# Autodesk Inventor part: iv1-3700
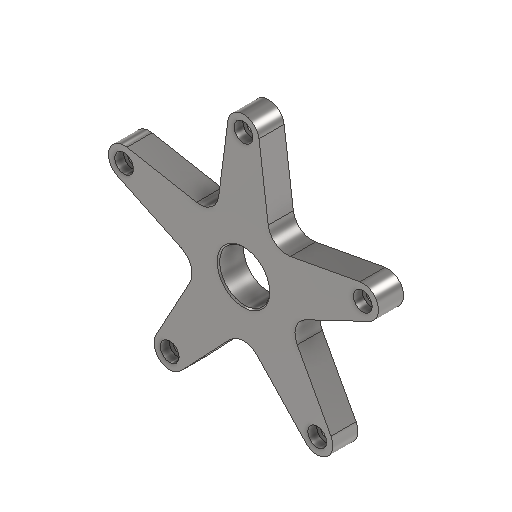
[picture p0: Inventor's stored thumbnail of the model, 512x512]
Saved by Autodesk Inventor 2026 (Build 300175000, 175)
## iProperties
Created: 2022-01
Part Number: iv1-3700
Material: Steel, Mild
Document SubType Name: Modeling
Designer: Lars Bertram Pedersen
Density: 7.85 g/cm^3
Appearance: Semi-Polished
Mass: 2365.55 g
Surface Area: 537.033 cm^2
Volume: 301.343 cm^3
Author: Lars Bertram Pedersen
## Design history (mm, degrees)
sketch "Sketch1"
  geometry: L1 (-12.393, 101.632)-(-25.773, 0); L2 (12.393, 101.632)-(25.773, 0); L3 (-25.773, 0)-(25.773, 0); C1 r 20 at (0, 0); A1 r 12.5 centre (0, 100) between (12.476, 99.219) and (-12.476, 99.219); A2 r 100 centre (0, 0) between (0, 100) and (-12.476, 99.219); 1 further point
  constraints: 7 point on circle, 6 end point, 3 centre point, 3 horizontal alignment, 2 coincident, 2 tangent, 1 horizontal, 1 vertical alignment
  dimensions: "d0" = 200 diameter of A2; "d1" = 40 diameter of C1; "d2" = 12.5 radius of A1; "d3" = 15 deg angle of L2 L1
extrude "Extrusion1" new body sketch "Sketch1" distance "d4" = 20; taper "d5" = 0 deg
pattern_circular "Circular Pattern1" dims angle "d7" = 360 deg
fillet "Fillet1" dims "d9" = 15
sketch "Sketch3"
  geometry: C1 r 20 at (0, 0); 1 further point
  constraints: 1 centre point, 1 coincident
  dimensions: "d17" = 40 diameter of C1
extrude "Extrusion2" cut sketch "Sketch3" extent not by distance; stored distance "d18" = 0; taper "d19" = 0 deg
sketch "Sketch2"
  geometry: L1 (-37.361, 32.912)-(-92.828, 43.192) reference; L2 (-100.487, 19.619)-(-49.571, -4.666) reference; L3 (-42.847, -25.362)-(-69.764, -74.937) reference; L4 (-49.711, -89.506)-(-10.881, -48.587) reference; L5 (10.881, -48.587)-(49.711, -89.506) reference; L6 (69.764, -74.937)-(42.847, -25.362) reference; L7 (49.571, -4.666)-(100.487, 19.619) reference; L8 (92.828, 43.192)-(37.361, 32.912) reference; L9 (19.756, 45.703)-(12.393, 101.632) reference; L10 (-12.393, 101.632)-(-19.756, 45.703) reference; A1 r 12.5 centre (-95.106, 30.902) between (-92.828, 43.192) and (-100.487, 19.619) reference; A2 r 15 centre (-56.029, -18.205) between (-42.847, -25.362) and (-49.571, -4.666) reference; A3 r 12.5 centre (-58.779, -80.902) between (-69.764, -74.937) and (-49.711, -89.506) reference; A4 r 15 centre (0, -58.912) between (10.881, -48.587) and (-10.881, -48.587) reference; A5 r 12.5 centre (58.779, -80.902) between (49.711, -89.506) and (69.764, -74.937) reference; A6 r 15 centre (56.029, -18.205) between (49.571, -4.666) and (42.847, -25.362) reference; A7 r 12.5 centre (95.106, 30.902) between (100.487, 19.619) and (92.828, 43.192) reference; A8 r 15 centre (34.628, 47.661) between (19.756, 45.703) and (37.361, 32.912) reference; A9 r 12.5 centre (0, 100) between (12.393, 101.632) and (-12.393, 101.632) reference; A10 r 15 centre (-34.628, 47.661) between (-37.361, 32.912) and (-19.756, 45.703) reference; 6 further points
  constraints: 5 coincident
hole "Hole1" sketch "Sketch2" diameter "d10" = 8.5; stored, may be unused: countersink angle "d14" = 90 deg, drill point angle "d16" = 118 deg; dims "d11" = 6, "d12" = 15, "d13" = 7, "d15" = 8
chamfer "Chamfer1" distance "d20" = 1; stored, may be unused: second distance "d21" = 2, angle "d22" = 45 deg
body "Solid1"
node "Projected Loop1"
